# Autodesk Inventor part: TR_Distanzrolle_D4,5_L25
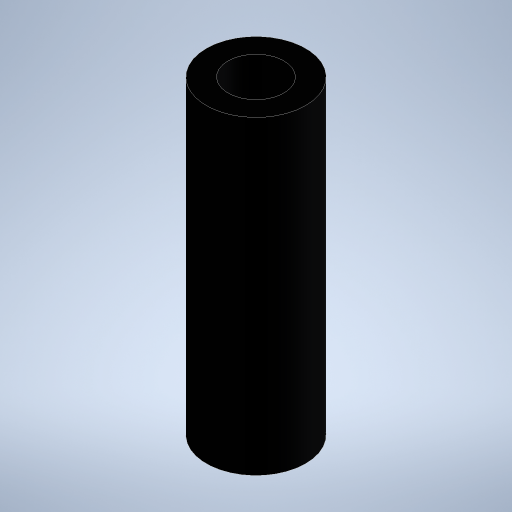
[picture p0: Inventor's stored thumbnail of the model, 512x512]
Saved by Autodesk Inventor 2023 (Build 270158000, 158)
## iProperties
Created: 2023-11
Part Number: TR_Distanzrolle_D4,5_L25
Material: PC/ABS-Kunststoff
Document SubType Name: Modeling
Designer: Admin
Density: 0.357273 g/cm^3
Appearance: Glatt - Schwarz
Author: Admin
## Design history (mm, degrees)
sketch "Skizze1"
  geometry: C1 r 2.25 at (0, 0); C2 r 4 at (0, 0); 1 further point
  constraints: 2 centre point, 2 coincident
  dimensions: "d0" = 4.5 diameter of C1; "d1" = 8 diameter of C2
extrude "Extrusion1" new body sketch "Skizze1" distance "d2" = 25; taper "d3" = 0 deg
node "Volumenkörper1"
